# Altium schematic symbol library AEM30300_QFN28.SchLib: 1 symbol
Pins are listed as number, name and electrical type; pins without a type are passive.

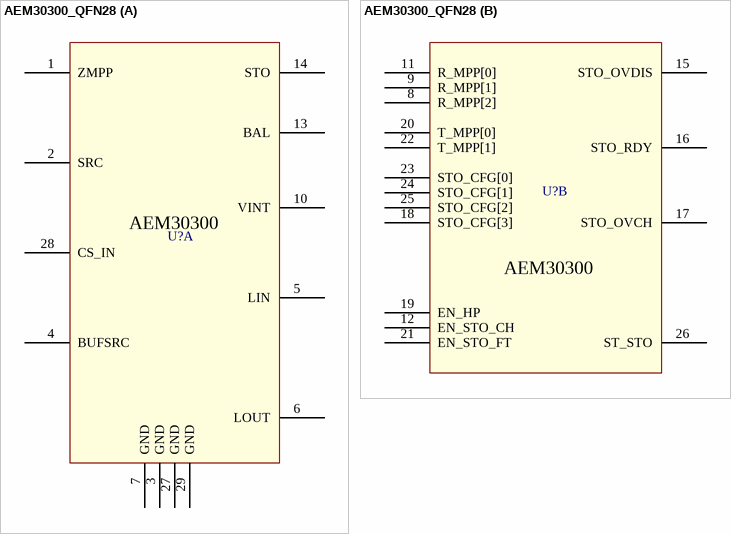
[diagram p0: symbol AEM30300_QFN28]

## AEM30300_QFN28
designator U?  (value not drawn)
footprint QFN28 4x4mm pitch=0.4mm Pad_0.23mm TPad 2.3mm (QFN, 28-Leads, Body 4.00x4.00mm, Pitch 0.40mm, Thermal Pad 2.60x2.60mm, IPC Medium Density)
part A pins: 1 ZMPP, 2 SRC, 3 GND, 4 BUFSRC, 5 LIN, 6 LOUT, 7 GND, 10 VINT, 13 BAL, 14 STO, 27 GND, 28 CS_IN, 29 GND
part B pins: 8 R_MPP[2], 9 R_MPP[1], 11 R_MPP[0], 12 EN_STO_CH, 15 STO_OVDIS, 16 STO_RDY, 17 STO_OVCH, 18 STO_CFG[3], 19 EN_HP, 20 T_MPP[0], 21 EN_STO_FT, 22 T_MPP[1], 23 STO_CFG[0], 24 STO_CFG[1], 25 STO_CFG[2], 26 ST_STO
